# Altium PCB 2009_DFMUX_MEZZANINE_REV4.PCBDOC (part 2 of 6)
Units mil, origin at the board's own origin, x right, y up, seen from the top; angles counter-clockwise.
Board outline 4922.86 x 3627.76 mil, 6 copper layers (Top Layer, Internal Plane 1, Mid-Layer 1, Internal Plane 2, Mid-Layer 2, Bottom Layer); 519 components, 606 nets, 2175 pads, 757 vias.
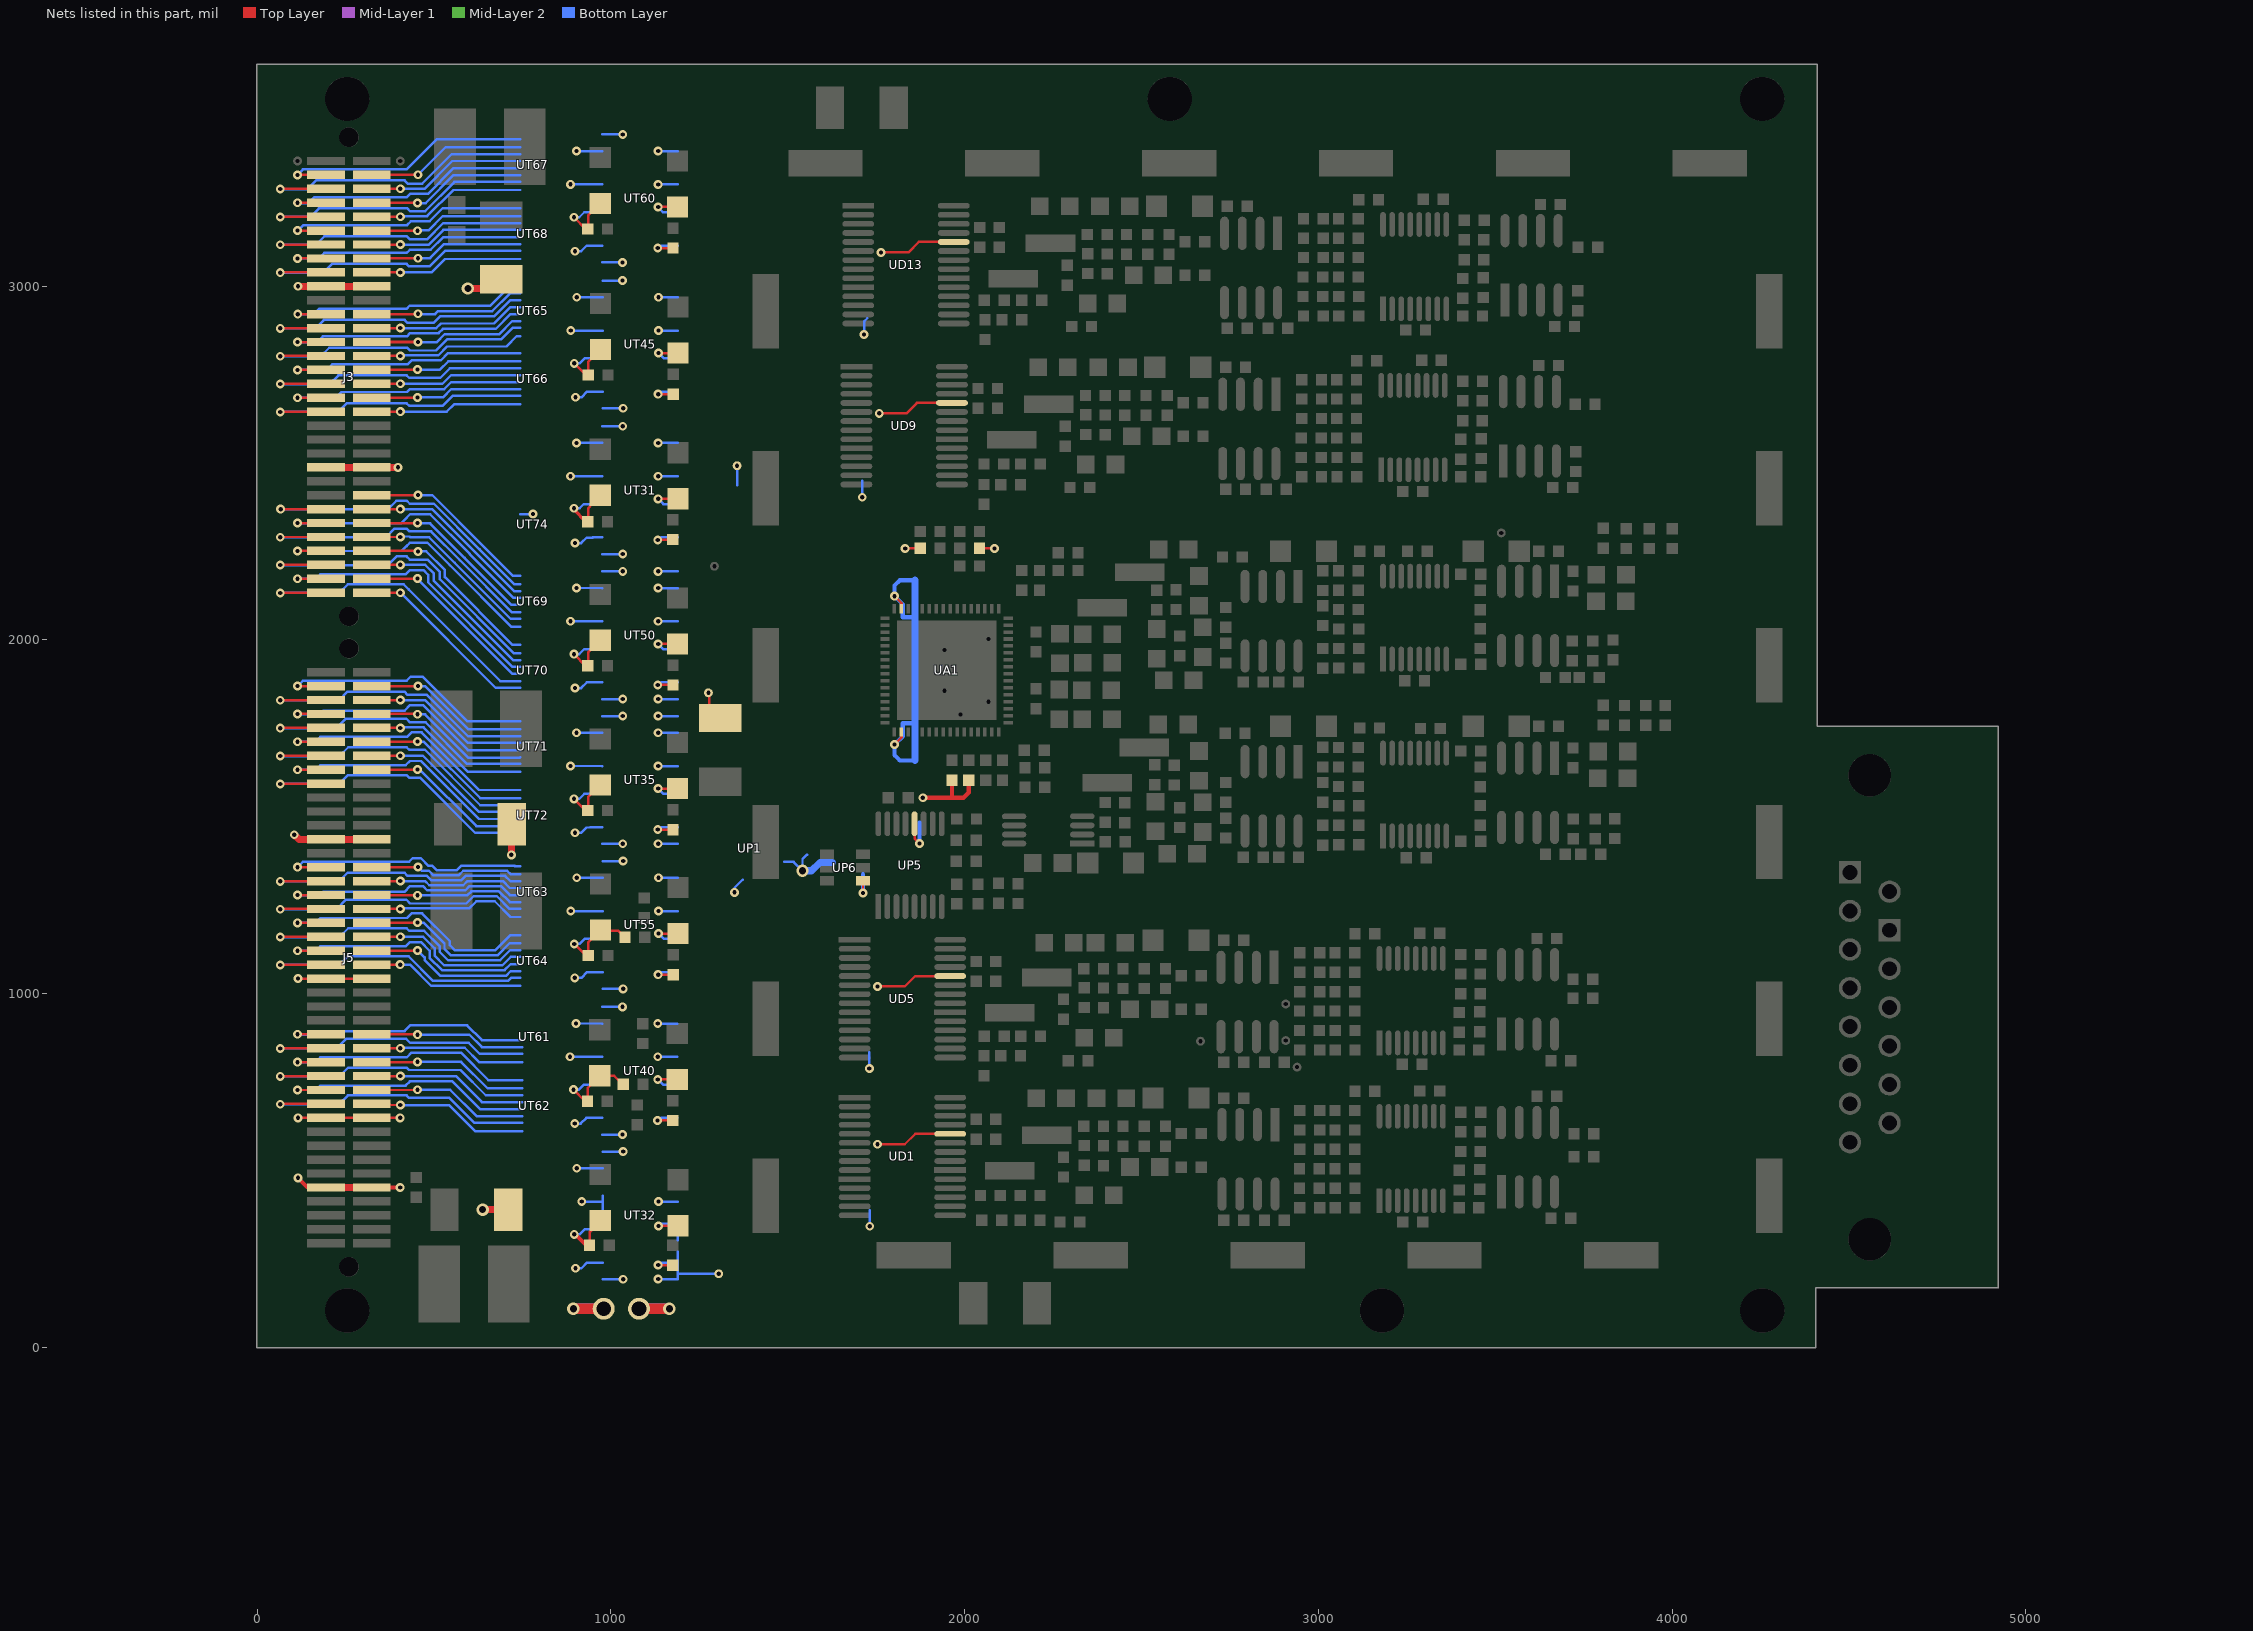
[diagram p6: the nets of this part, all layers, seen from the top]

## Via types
v1: diameter 25, hole 12, Top Layer to Bottom Layer, 692 vias
v2: diameter 40, hole 20, Top Layer to Bottom Layer, 39 vias
v3: diameter 35, hole 20, Top Layer to Bottom Layer, 23 vias
v4: diameter 22, hole 12, Top Layer to Bottom Layer, 3 vias

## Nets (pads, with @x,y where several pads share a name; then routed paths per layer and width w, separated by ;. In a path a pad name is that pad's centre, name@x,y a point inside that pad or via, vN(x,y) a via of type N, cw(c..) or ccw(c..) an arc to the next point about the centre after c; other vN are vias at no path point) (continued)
COMB1_DATA4: J5.53 UT61.12 | length 743.5
  Top Layer w7: v1(114.33,884.83) J5.53@194.63,884.83
  Bottom Layer w7: v1(114.33,884.83) 115.3,883.87 176.63,883.87 186.63,893.87 416.63,893.87 432.63,909.87 593.77,909.87 635.27,868.37 UT61.12@749.13,868.37
COMB1_DATA5: J5.54 UT61.11 | length 439.7
  Top Layer w7: J5.54@324.55,884.83 452.67,884.83 v1(453.63,883.87)
  Bottom Layer w7: v1(453.63,883.87) 599.77,883.87 635.27,848.37 UT61.11@749.13,848.37
COMB1_DATA6: J5.55 UT61.10 | length 841.8
  Top Layer w7: v1(65.55,844.7) 66.32,845.47 J5.55@194.63,845.47
  Bottom Layer w7: v1(65.55,844.7) 224.47,844.7 251.63,871.87 421.63,871.87 432.63,860.87 597.77,860.87 629.27,829.37 UT61.10@749.13,829.37
COMB1_DATA7: J5.56 UT61.9 | length 441.9
  Top Layer w7: J5.56@324.55,845.47 v1(404.85,845.47)
  Bottom Layer w7: v1(404.85,845.47) 406.45,846.87 586.77,846.87 627.27,806.37 UT61.9@749.13,806.37
COMB1_DATA8: J5.57 UT62.16 | length 758.5
  Top Layer w7: v1(114.33,806.1) J5.57@194.63,806.1
  Bottom Layer w7: v1(114.33,806.1) 114.57,805.87 164.63,805.87 178.63,819.87 423.63,819.87 436.63,832.87 575.77,832.87 653.27,755.37 UT62.16@749.13,755.37
COMB1_DATA9: J5.58 UT62.15 | length 455.8
  Top Layer w7: J5.58@324.55,806.1 452.87,806.1 v1(453.63,806.87)
  Bottom Layer w7: v1(453.63,806.87) 576.77,806.87 651.27,732.37 UT62.15@749.13,732.37
COMB1_DATA10: J5.59 UT62.14 | length 855.8
  Top Layer w7: v1(65.55,765.97) 66.32,766.73 J5.59@194.63,766.73
  Bottom Layer w7: v1(65.55,765.97) 232.73,765.97 257.63,790.87 422.63,790.87 429.63,783.87 574.77,783.87 646.27,712.37 UT62.14@749.13,712.37
COMB1_DATA11: J5.60 UT62.13 | length 455
  Top Layer w7: J5.60@324.55,766.73 v1(404.85,766.73)
  Bottom Layer w7: v1(404.85,766.73) 561.9,766.73 635.27,693.37 UT62.13@749.13,693.37
COMB1_DATA12: J5.61 UT62.12 | length 757.8
  Top Layer w7: v1(114.33,727.37) J5.61@194.63,727.37
  Bottom Layer w7: v1(114.33,727.37) 166.13,727.37 178.63,739.87 419.63,739.87 431.63,751.87 551.77,751.87 630.27,673.37 UT62.12@749.13,673.37
COMB1_DATA13: J5.62 UT62.11 | length 455.9
  Top Layer w7: J5.62@324.55,727.37 452.87,727.37 v1(453.63,728.13)
  Bottom Layer w7: v1(453.63,728.13) 545.5,728.13 620.27,653.37 UT62.11@749.13,653.37
COMB1_DATA14: J5.63 UT62.10 | length 855.3
  Top Layer w7: v1(65.55,687.23) 66.32,688 J5.63@194.63,688
  Bottom Layer w7: v1(65.55,687.23) 232,687.23 256.63,711.87 422.63,711.87 429.63,704.87 543.77,704.87 614.27,634.37 UT62.10@749.13,634.37
COMB1_DATA15: J5.64 UT62.9 | length 455
  Top Layer w7: J5.64@324.55,688 v1(404.85,684.73)
  Bottom Layer w7: v1(404.85,684.73) 542.9,684.73 616.27,611.37 UT62.9@749.13,611.37
COMB2_DATA0: J5.29 UT63.16 | length 740.4
  Top Layer w7: v1(114.33,1357.23) J5.29@194.63,1357.23
  Bottom Layer w7: v1(114.33,1357.23) 129.63,1372.53 429.8,1372.53 439.63,1382.37 463.27,1382.37 484.63,1361 495.63,1361 508.63,1348 563.63,1348 576.63,1361 727.63,1361 728.27,1360.37 UT63.16@744.13,1360.37
COMB2_DATA1: J5.30 UT63.15 | length 438.8
  Top Layer w7: J5.30@324.55,1357.23 453.33,1357.23 453.63,1357.53 v1(454.63,1357.53)
  Bottom Layer w7: v1(454.63,1357.53) 455.1,1357.53 465.63,1347 485.63,1347 498.63,1334 569.63,1334 582.63,1347 706.63,1347 716.27,1337.37 UT63.15@744.13,1337.37
COMB2_DATA2: J5.31 UT63.14 | length 838.5
  Top Layer w7: v1(65.55,1317.1) 66.32,1317.87 J5.31@194.63,1317.87
  Bottom Layer w7: v1(65.55,1317.1) 231.2,1317.1 255.63,1341.53 416.63,1341.53 425.63,1332.53 480.1,1332.53 492.63,1320 576.63,1320 589.17,1332.53 701.1,1332.53 716.27,1317.37 UT63.14@744.13,1317.37
COMB2_DATA3: J5.32 UT63.13 | length 437.5
  Top Layer w7: J5.32@324.55,1317.87 v1(404.85,1317.87)
  Bottom Layer w7: v1(404.85,1317.87) 474.77,1317.87 486.63,1306 582.63,1306 594.5,1317.87 694.63,1317.87 714.13,1298.37 UT63.13@744.13,1298.37
COMB2_DATA4: J5.33 UT63.12 | length 741.2
  Top Layer w7: v1(114.33,1278.5) J5.33@194.63,1278.5
  Bottom Layer w7: v1(114.33,1278.5) 115.3,1277.53 176.63,1277.53 186.63,1287.53 416.63,1287.53 432.63,1303.53 469.1,1303.53 480.63,1292 588.63,1292 600.17,1303.53 689.1,1303.53 714.27,1278.37 UT63.12@744.13,1278.37
COMB2_DATA5: J5.34 UT63.11 | length 437.4
  Top Layer w7: J5.34@324.55,1278.5 452.67,1278.5 v1(453.63,1277.53)
  Bottom Layer w7: v1(453.63,1277.53) 454.1,1278 594.63,1278 605.63,1289 683.63,1289 714.27,1258.37 UT63.11@744.13,1258.37
COMB2_DATA6: J5.35 UT63.10 | length 847
  Top Layer w7: v1(65.55,1238.37) 66.32,1239.13 J5.35@194.63,1239.13
  Bottom Layer w7: v1(65.55,1238.37) 224.47,1238.37 251.63,1265.53 421.63,1265.53 432.63,1254.53 591.17,1254.53 611.63,1275 677.63,1275 713.27,1239.37 UT63.10@744.13,1239.37
COMB2_DATA7: J5.36 UT63.9 | length 447.1
  Top Layer w7: J5.36@324.55,1239.13 v1(404.85,1239.13)
  Bottom Layer w7: v1(404.85,1239.13) 406.45,1240.53 599.17,1240.53 619.63,1261 671.63,1261 716.27,1216.37 UT63.9@744.13,1216.37
COMB2_DATA8: J5.37 UT64.16 | length 789.1
  Top Layer w7: v1(114.33,1199.77) J5.37@194.63,1199.77
  Bottom Layer w7: v1(114.33,1199.77) 114.57,1199.53 164.63,1199.53 178.63,1213.53 423.63,1213.53 436.63,1226.53 466.1,1226.53 544.63,1148 544.63,1137 559.63,1122 672.63,1122 716,1165.37 UT64.16@744.13,1165.37
COMB2_DATA9: J5.38 UT64.15 | length 481.3
  Top Layer w7: J5.38@324.55,1199.77 452.87,1199.77 v1(453.63,1200.53)
  Bottom Layer w7: v1(453.63,1200.53) 470.1,1200.53 529.63,1141 529.63,1126 547.63,1108 679.63,1108 714,1142.37 UT64.15@744.13,1142.37
COMB2_DATA10: J5.39 UT64.14 | length 876.9
  Top Layer w7: v1(65.55,1159.63) 66.32,1160.4 J5.39@194.63,1160.4
  Bottom Layer w7: v1(65.55,1159.63) 232.73,1159.63 257.63,1184.53 422.63,1184.53 429.63,1177.53 472.1,1177.53 515.63,1134 515.63,1118 539.63,1094 686.63,1094 715,1122.37 UT64.14@744.13,1122.37
COMB2_DATA11: J5.40 UT64.13 | length 474.9
  Top Layer w7: J5.40@324.55,1160.4 v1(404.85,1160.4)
  Bottom Layer w7: v1(404.85,1160.4) 469.23,1160.4 501.63,1128 501.63,1107 528.63,1080 693.63,1080 717,1103.37 UT64.13@744.13,1103.37
COMB2_DATA12: J5.41 UT64.12 | length 772.1
  Top Layer w7: v1(114.33,1121.03) J5.41@194.63,1121.03
  Bottom Layer w7: v1(114.33,1121.03) 166.13,1121.03 178.63,1133.53 419.63,1133.53 431.63,1145.53 463.1,1145.53 487.63,1121 487.63,1101 522.63,1066 699.63,1066 717,1083.37 UT64.12@744.13,1083.37
COMB2_DATA13: J5.42 UT64.11 | length 459.3
  Top Layer w7: J5.42@324.55,1121.03 452.87,1121.03 v1(453.63,1121.8)
  Bottom Layer w7: v1(453.63,1121.8) 453.83,1121.8 473.63,1102 473.63,1095 518.63,1050 703.63,1050 717,1063.37 UT64.11@744.13,1063.37
COMB2_DATA14: J5.43 UT64.10 | length 850.5
  Top Layer w7: v1(65.55,1080.9) 66.32,1081.67 J5.43@194.63,1081.67
  Bottom Layer w7: v1(65.55,1080.9) 232,1080.9 256.63,1105.53 428.1,1105.53 497.63,1036 709.63,1036 718,1044.37 UT64.10@744.13,1044.37
COMB2_DATA15: J5.44 UT64.9 | length 444.6
  Top Layer w7: J5.44@324.55,1081.67 v1(404.33,1081.67)
  Bottom Layer w7: v1(404.33,1081.67) 431.97,1081.67 492.27,1021.37 UT64.9@744.13,1021.37
COMB3_DATA0: J3.23 UT65.16 | length 746.9
  Top Layer w7: v1(114.67,2920.4) J3.23@194.63,2920.4
  Bottom Layer w7: v1@112.03,2918 v1(114.67,2920.4) ; v1@114.7,2920.37 159.63,2920.37 175.63,2936.37 423.3,2936.37 431.3,2944.37 659.63,2944.37 718,3002.37 UT65.16@744.13,3002.37
COMB3_DATA1: J3.24 UT65.15 | length 446.8
  Top Layer w7: J3.24@324.55,2920.4 453.33,2920.4 v1@453.63,2920.7 ; v1@453.63,2920.7 454.63,2920.7 v1(454.63,2921.37) 453.63,2921.37 v1@453.63,2920.7
  Bottom Layer w7: v1(454.63,2921.37) 455.63,2920.37 502.63,2920.37 503.3,2920.7 511.6,2929 664.63,2929 715,2979.37 UT65.15@744.13,2979.37
COMB3_DATA2: J3.25 UT65.14 | length 847.9
  Top Layer w7: v1(65.55,2880.27) 66.32,2881.03 J3.25@194.63,2881.03
  Bottom Layer w7: v1(65.55,2880.27) 164.53,2880.27 188.63,2904.37 416.97,2904.37 425.63,2895.7 498.97,2895.7 517.27,2914 669.63,2914 715,2959.37 UT65.14@744.13,2959.37
COMB3_DATA3: J3.26 UT65.13 | length 444.2
  Top Layer w7: J3.26@324.55,2881.03 v1(404.85,2881.03)
  Bottom Layer w7: v1(404.85,2881.03) 506.3,2881.03 519.27,2894 669.63,2894 716,2940.37 UT65.13@744.13,2940.37
COMB3_DATA4: J3.27 UT65.12 | length 743.5
  Top Layer w7: v1(114.33,2841.67) J3.27@194.63,2841.67
  Bottom Layer w7: v1(114.33,2841.67) 115.3,2840.7 168.73,2840.7 185.73,2857.37 423.63,2857.37 432.63,2866.7 512.97,2866.7 525.27,2879 674.63,2879 716,2920.37 UT65.12@744.13,2920.37
COMB3_DATA5: J3.28 UT65.11 | length 576.5
  Top Layer w7: J3.28@324.55,2841.67 324.88,2842 v1(454.63,2842) 453.97,2841.67 J3.28@324.55,2841.67
  Bottom Layer w7: v1@454,2841.37 v1(454.63,2842) 453.97,2841.67 507.93,2841.67 530.27,2864 684.63,2864 721,2900.37 UT65.11@744.13,2900.37
COMB3_DATA6: J3.29 UT65.10 | length 847.2
  Top Layer w7: v1(65.55,2801.53) 66.32,2802.3 J3.29@194.63,2802.3
  Bottom Layer w7: v1(65.55,2801.53) 179.65,2801.53 203.82,2825.37 424.63,2825.37 432.63,2817.7 505.97,2817.7 537.27,2849 689.63,2849 722,2881.37 UT65.10@744.13,2881.37
COMB3_DATA7: J3.30 UT65.9 | length 442.8
  Top Layer w7: J3.30@324.55,2802.3 v1(404.85,2802.3)
  Bottom Layer w7: v1(404.85,2802.3) 406.45,2803.7 511.97,2803.7 537.27,2829 704.63,2829 734,2858.37 UT65.9@744.13,2858.37
COMB3_DATA8: J3.31 UT66.16 | length 729.8
  Top Layer w7: v1(114.33,2762.93) J3.31@194.63,2762.93
  Bottom Layer w7: v1(114.33,2762.93) 114.57,2762.7 195.97,2762.7 210.97,2777.37 211.97,2778.37 425.3,2778.37 436.63,2789.7 518.97,2789.7 539.63,2810.37 UT66.16@744.13,2810.37
COMB3_DATA9: J3.32 UT66.15 | length 429.7
  Top Layer w7: J3.32@324.55,2762.93 452.87,2762.93 v1(453.63,2763.7)
  Bottom Layer w7: v1(453.63,2763.7) 516.97,2763.7 540.63,2787.37 UT66.15@744.13,2787.37
COMB3_DATA10: J3.33 UT66.14 | length 831.8
  Top Layer w7: v1(65.55,2722.8) 66.32,2723.57 J3.33@194.63,2723.57
  Bottom Layer w7: v1(65.55,2722.8) 204.9,2722.8 229.8,2747.37 422.63,2747.37 429.63,2740.7 517.97,2740.7 544.63,2767.37 UT66.14@744.13,2767.37
COMB3_DATA11: J3.34 UT66.13 | length 429.9
  Top Layer w7: J3.34@324.55,2723.57 v1(404.85,2723.57)
  Bottom Layer w7: v1(404.85,2723.57) 523.83,2723.57 548.63,2748.37 UT66.13@744.13,2748.37
COMB3_DATA12: J3.35 UT66.12 | length 728.4
  Top Layer w7: v1(114.33,2684.2) J3.35@194.63,2684.2
  Bottom Layer w7: v1(114.33,2684.2) 222.3,2684.2 238.8,2700.37 423.63,2700.37 431.63,2708.7 528.97,2708.7 548.63,2728.37 UT66.12@744.13,2728.37
COMB3_DATA13: J3.36 UT66.11 | length 429.6
  Top Layer w7: J3.36@324.55,2684.2 452.87,2684.2 v1(453.63,2684.97)
  Bottom Layer w7: v1(453.63,2684.97) 525.23,2684.97 548.63,2708.37 UT66.11@744.13,2708.37
COMB3_DATA14: J3.37 UT66.10 | length 832.1
  Top Layer w7: v1(65.55,2644.07) 66.32,2644.83 J3.37@194.63,2644.83
  Bottom Layer w7: v1(65.55,2644.07) 228.15,2644.07 252.78,2668.37 422.63,2668.37 429.63,2661.7 524.97,2661.7 552.63,2689.37 UT66.10@744.13,2689.37
COMB3_DATA15: J3.38 UT66.9 | length 428.5
  Top Layer w7: J3.38@324.55,2644.83 v1(404.85,2644.83)
  Bottom Layer w7: v1(404.85,2644.83) 536.1,2644.83 557.63,2666.37 UT66.9@744.13,2666.37
COMB4_DATA0: J3.3 UT67.16 | length 752.1
  Top Layer w7: v1(114.33,3314.07) J3.3@194.63,3314.07
  Bottom Layer w7: v1(114.33,3314.07) 129.63,3329.37 422.63,3329.37 508.63,3415.37 UT67.16@744.13,3415.37
COMB4_DATA1: J3.4 UT67.15 | length 452
  Top Layer w7: J3.4@324.55,3314.07 453.33,3314.07 453.63,3314.37 v1(454.63,3314.37)
  Bottom Layer w7: v1(454.63,3314.37) 532.63,3392.37 UT67.15@744.13,3392.37
COMB4_DATA2: J3.5 UT67.14 | length 856.2
  Top Layer w7: v1(65.55,3273.93) 66.32,3274.7 J3.5@194.63,3274.7
  Bottom Layer w7: v1(65.55,3273.93) 142.2,3273.93 166.63,3298.37 416.63,3298.37 425.63,3289.37 466.63,3289.37 549.63,3372.37 UT67.14@744.13,3372.37
COMB4_DATA3: J3.6 UT67.13 | length 452.2
  Top Layer w7: J3.6@324.55,3274.7 v1(404.85,3274.7)
  Bottom Layer w7: v1(404.85,3274.7) 472.97,3274.7 551.63,3353.37 UT67.13@744.13,3353.37
COMB4_DATA4: J3.7 UT67.12 | length 751.5
  Top Layer w7: v1(114.33,3235.33) J3.7@194.63,3235.33
  Bottom Layer w7: v1(114.33,3235.33) 115.3,3234.37 145.63,3234.37 162.63,3251.37 423.63,3251.37 432.63,3260.37 482.63,3260.37 555.63,3333.37 UT67.12@744.13,3333.37
COMB4_DATA5: J3.8 UT67.11 | length 452.7
  Top Layer w7: J3.8@324.55,3235.33 452.67,3235.33 v1(453.63,3234.37)
  Bottom Layer w7: v1(453.63,3234.37) 476.63,3234.37 555.63,3313.37 UT67.11@744.13,3313.37
COMB4_DATA6: J3.9 UT67.10 | length 855.7
  Top Layer w7: v1(65.55,3195.2) 66.32,3195.97 J3.9@194.63,3195.97
  Bottom Layer w7: v1(65.55,3195.2) 150.47,3195.2 174.63,3219.37 424.63,3219.37 432.63,3211.37 474.63,3211.37 557.63,3294.37 UT67.10@744.13,3294.37
COMB4_DATA7: J3.10 UT67.9 | length 451
  Top Layer w7: J3.10@324.55,3195.97 v1(404.85,3195.97)
  Bottom Layer w7: v1(404.85,3195.97) 405.25,3196.37 405.85,3196.37 406.45,3197.37 480.63,3197.37 554.63,3271.37 UT67.9@744.13,3271.37
COMB4_DATA8: J3.11 UT68.16 | length 736.8
  Top Layer w7: v1(114.33,3156.6) J3.11@194.63,3156.6
  Bottom Layer w7: v1(114.33,3156.6) 114.57,3156.37 130.57,3172.37 423.83,3172.37 434.63,3183 487.63,3183 524.63,3220.37 UT68.16@744.13,3220.37
COMB4_DATA9: J3.12 UT68.15 | length 437.9
  Top Layer w7: J3.12@324.55,3156.6 454.03,3156.6 v1(453.63,3156)
  Bottom Layer w7: v1(453.63,3156) 454.03,3156.6 454.8,3157.37 484.63,3157.37 524.63,3197.37 UT68.15@744.13,3197.37
COMB4_DATA10: J3.13 UT68.14 | length 840.1
  Top Layer w7: v1(65.55,3116.47) 66.32,3117.23 J3.13@194.63,3117.23
  Bottom Layer w7: v1(65.55,3116.47) 165.73,3116.47 189.63,3140.37 423.63,3140.37 432,3132 480.27,3132 525.63,3177.37 UT68.14@744.13,3177.37
COMB4_DATA11: J3.14 UT68.13 | length 436.6
  Top Layer w7: J3.14@324.55,3117.23 v1(404.85,3117.23)
  Bottom Layer w7: v1(404.85,3117.23) 485.5,3117.23 526.63,3158.37 UT68.13@744.13,3158.37
COMB4_DATA12: J3.15 UT68.12 | length 735.2
  Top Layer w7: v1(114.33,3077.87) J3.15@194.63,3077.87
  Bottom Layer w7: v1(114.33,3077.87) 174.13,3077.87 189.63,3093.37 422.63,3093.37 431.63,3102.37 490.63,3102.37 526.63,3138.37 UT68.12@744.13,3138.37
COMB4_DATA13: J3.16 UT68.11 | length 568.7
  Top Layer w7: J3.16@324.55,3077.87 453.33,3077.87 453.83,3078.37 v1(454.63,3078.37) 453.63,3078.63 452.87,3077.87 J3.16@324.55,3077.87
  Bottom Layer w7: v1(454.63,3078.37) 453.63,3078.63 488.9,3078.63 528.63,3118.37 UT68.11@744.13,3118.37
COMB4_DATA14: J3.17 UT68.10 | length 839.3
  Top Layer w7: v1(65.55,3037.73) 66.32,3038.5 J3.17@194.63,3038.5
  Bottom Layer w7: v1(65.55,3037.73) 187,3037.73 211.63,3062.37 422.63,3062.37 429.63,3055.37 487.63,3055.37 531.63,3099.37 UT68.10@744.13,3099.37
COMB4_DATA15: J3.18 UT68.9 | length 435.3
  Top Layer w7: J3.18@324.55,3038.5 v1(404.85,3038.5)
  Bottom Layer w7: v1(404.85,3038.5) 492.77,3038.5 530.63,3076.37 UT68.9@744.13,3076.37
DEMODA_DATA0: J5.3 UT71.16 | length 773.3
  Top Layer w7: v1(114.33,1869) J5.3@194.63,1869
  Bottom Layer w7: v1(114.33,1869) 129.63,1884.3 422.63,1884.3 434.3,1895.97 468.03,1895.97 593.63,1770.37 UT71.16@744.13,1770.37
DEMODA_DATA1: J5.4 UT71.15 | length 470.2
  Top Layer w7: J5.4@324.55,1869 453.33,1869 453.63,1869.3 v1(454.63,1869.3)
  Bottom Layer w7: v1(454.63,1869.3) 474.7,1869.3 596.63,1747.37 UT71.15@744.13,1747.37
DEMODA_DATA2: J5.5 UT71.14 | length 870.3
  Top Layer w7: v1(65.55,1828.87) 66.32,1829.63 J5.5@194.63,1829.63
  Bottom Layer w7: v1(65.55,1828.87) 231.2,1828.87 255.63,1853.3 416.63,1853.3 425.63,1844.3 479.7,1844.3 596.63,1727.37 UT71.14@744.13,1727.37
DEMODA_DATA3: J5.6 UT71.13 | length 469.8
  Top Layer w7: J5.6@324.55,1829.63 v1(404.85,1829.63)
  Bottom Layer w7: v1(404.85,1829.63) 474.37,1829.63 595.63,1708.37 UT71.13@744.13,1708.37
DEMODA_DATA4: J5.7 UT71.12 | length 773.8
  Top Layer w7: v1(114.33,1790.27) J5.7@194.63,1790.27
  Bottom Layer w7: v1(114.33,1790.27) 115.3,1789.3 176.63,1789.3 186.63,1799.3 416.63,1799.3 432.63,1815.3 468.7,1815.3 595.63,1688.37 UT71.12@744.13,1688.37
DEMODA_DATA5: J5.8 UT71.11 | length 471.7
  Top Layer w7: J5.8@324.55,1790.27 452.67,1790.27 v1(453.63,1789.3)
  Bottom Layer w7: v1(453.63,1789.3) 474.7,1789.3 597.63,1666.37 742.13,1666.37 UT71.11@744.13,1668.37
DEMODA_DATA6: J5.9 UT71.10 | length 872.2
  Top Layer w7: v1(65.55,1750.13) 66.32,1750.9 J5.9@194.63,1750.9
  Bottom Layer w7: v1(65.55,1750.13) 224.47,1750.13 251.63,1777.3 421.63,1777.3 432.63,1766.3 476.7,1766.3 593.63,1649.37 UT71.10@744.13,1649.37
DEMODA_DATA7: J5.10 UT71.9 | length 472.3
  Top Layer w7: J5.10@324.55,1750.9 v1(404.85,1750.9)
  Bottom Layer w7: v1(404.85,1750.9) 406.45,1752.3 470.7,1752.3 596.63,1626.37 UT71.9@744.13,1626.37
DEMODA_DATA8: J5.11 UT72.16 | length 788.9
  Top Layer w7: v1(114.33,1711.53) J5.11@194.63,1711.53
  Bottom Layer w7: v1(114.33,1711.53) 114.57,1711.3 164.63,1711.3 178.63,1725.3 423.63,1725.3 436.63,1738.3 464.7,1738.3 627.63,1575.37 UT72.16@744.13,1575.37
DEMODA_DATA9: J5.12 UT72.15 | length 486.1
  Top Layer w7: J5.12@324.55,1711.53 452.87,1711.53 v1(453.63,1712.3)
  Bottom Layer w7: v1(453.63,1712.3) 470.7,1712.3 630.63,1552.37 UT72.15@744.13,1552.37
DEMODA_DATA10: J5.13 UT72.14 | length 886.2
  Top Layer w7: v1(65.55,1671.4) 66.32,1672.17 J5.13@194.63,1672.17
  Bottom Layer w7: v1(65.55,1671.4) 232.73,1671.4 257.63,1696.3 422.63,1696.3 429.63,1689.3 473.7,1689.3 630.63,1532.37 UT72.14@744.13,1532.37
DEMODA_DATA11: J5.14 UT72.13 | length 485.4
  Top Layer w7: J5.14@324.55,1672.17 v1(404.85,1672.17)
  Bottom Layer w7: v1(404.85,1672.17) 468.83,1672.17 627.63,1513.37 UT72.13@744.13,1513.37
DEMODA_DATA12: J5.15 UT72.12 | length 788.2
  Top Layer w7: v1(114.33,1632.8) J5.15@194.63,1632.8
  Bottom Layer w7: v1(114.33,1632.8) 166.13,1632.8 178.63,1645.3 419.63,1645.3 431.63,1657.3 463.7,1657.3 627.63,1493.37 UT72.12@744.13,1493.37
DEMODA_DATA13: J5.16 UT72.11 | length 486.3
  Top Layer w7: J5.16@324.55,1632.8 452.87,1632.8 v1(453.63,1633.57)
  Bottom Layer w7: v1(453.63,1633.57) 459.43,1633.57 619.63,1473.37 UT72.11@744.13,1473.37
DEMODA_DATA14: J5.17 UT72.10 | length 885.7
  Top Layer w7: v1(65.55,1592.67) 66.32,1593.43 J5.17@194.63,1593.43
  Bottom Layer w7: v1(65.55,1592.67) 232,1592.67 256.63,1617.3 422.63,1617.3 429.63,1610.3 460.7,1610.3 616.63,1454.37 UT72.10@744.13,1454.37
DEMODB_DATA0: J3.50 UT69.16 | length 514.6
  Top Layer w7: J3.50@324.55,2408.63 453.33,2408.63 453.63,2408.93 v1(454.63,2408.93)
  Bottom Layer w7: v1(454.63,2408.93) 495.07,2408.93 642.63,2261.37 642.63,2261 723.27,2180.37 UT69.16@744.13,2180.37
DEMODB_DATA1: J3.51 UT69.15 | length 915.1
  Top Layer w7: v1@64.9,2369.27 v1(66.55,2369.27) J3.51@194.63,2369.27
  Bottom Layer w7: v1(66.55,2369.27) 369.98,2369.27 393.62,2393.13 422.63,2393.13 431.4,2384.37 499.63,2384.37 628.63,2255.37 628.63,2255 726.27,2157.37 UT69.15@744.13,2157.37
DEMODB_DATA2: J3.52 UT69.14 | length 515.9
  Top Layer w7: J3.52@324.55,2369.27 v1(404.85,2369.27)
  Bottom Layer w7: v1(404.85,2369.27) 494.73,2369.27 614.63,2249.37 614.63,2249 726.27,2137.37 UT69.14@744.13,2137.37
DEMODB_DATA3: J3.53 UT69.13 | length 819.5
  Top Layer w7: v1(114.33,2329.9) J3.53@194.63,2329.9
  Bottom Layer w7: v1(114.33,2329.9) 115.3,2328.93 406.57,2328.93 416.57,2338.93 416.63,2338.93 432.63,2354.93 489.07,2354.93 600.63,2243.37 600.63,2243 725.27,2118.37 UT69.13@744.13,2118.37
DEMODB_DATA4: J3.54 UT69.12 | length 516.1
  Top Layer w7: J3.54@324.55,2329.9 453.17,2329.9 v1(453.63,2330.37)
  Bottom Layer w7: v1(453.63,2330.37) 455.07,2328.93 489.07,2328.93 586.63,2231.37 586.63,2231 719.27,2098.37 UT69.12@744.13,2098.37
DEMODB_DATA5: J3.55 UT69.11 | length 916.2
  Top Layer w7: v1(65.55,2289.77) 66.32,2290.53 J3.55@194.63,2290.53
  Bottom Layer w7: v1(65.55,2289.77) 363.63,2289.77 388.27,2314.4 422.63,2314.4 430.67,2306.37 491.63,2306.37 572.63,2225.37 572.63,2225 719.27,2078.37 UT69.11@744.13,2078.37
DEMODB_DATA6: J3.56 UT69.10 | length 516.9
  Top Layer w7: J3.56@324.55,2290.53 v1(404.85,2290.53)
  Bottom Layer w7: v1(404.85,2290.53) 405.25,2290.93 405.85,2290.93 406.45,2291.93 431.07,2291.93 433.63,2289.37 486.63,2289.37 558.63,2217.37 558.63,2217 716.27,2059.37 UT69.10@744.13,2059.37
DEMODB_DATA7: J3.57 UT69.9 | length 818.8
  Top Layer w7: v1(114.33,2251.17) J3.57@194.63,2251.17
  Bottom Layer w7: v1(114.33,2251.17) 114.57,2250.93 408.57,2250.93 422.57,2264.93 422.8,2264.93 431.8,2274.37 481.63,2274.37 544.63,2211.37 544.63,2211 719.27,2036.37 UT69.9@744.13,2036.37
DEMODB_DATA8: J3.58 UT70.16 | length 542.6
  Top Layer w7: J3.58@324.55,2251.17 452.87,2251.17 v1@454.63,2249.4
  Bottom Layer w7: v1(454.63,2249.37) 455.2,2250.37 477.63,2250.37 530.63,2197.37 530.63,2177 722.27,1985.37 UT70.16@744.13,1985.37
DEMODB_DATA9: J3.59 UT70.15 | length 943.4
  Top Layer w7: v1(65.55,2211.03) 66.32,2211.8 J3.59@194.63,2211.8
  Bottom Layer w7: v1(65.55,2211.03) 369.67,2211.03 394.3,2235.67 422.63,2235.67 431.63,2226.37 481.63,2226.37 516.63,2191.37 516.63,2171 725.27,1962.37 UT70.15@744.13,1962.37
DEMODB_DATA10: J3.60 UT70.14 | length 545.9
  Top Layer w7: J3.60@324.55,2211.8 v1(404.85,2211.8)
  Mid-Layer 1 w7: v1@403.28,2213.37 v1(404.85,2211.8)
  Bottom Layer w7: v1(404.85,2211.8) 475.2,2211.8 498.63,2188.37 498.63,2167 723.27,1942.37 UT70.14@744.13,1942.37
DEMODB_DATA11: J3.61 UT70.13 | length 846.1
  Top Layer w7: v1(114.33,2172.43) J3.61@194.63,2172.43
  Bottom Layer w7: v1(114.33,2172.43) 166.13,2172.43 178.63,2184.93 419.63,2184.93 431.63,2196.93 470.07,2196.93 483.63,2183.37 483.63,2162 722.27,1923.37 UT70.13@744.13,1923.37
DEMODB_DATA12: J3.62 UT70.12 | length 532.5
  Top Layer w7: J3.62@324.55,2172.43 452.87,2172.43 v1(453.63,2173.2)
  Bottom Layer w7: v1(453.63,2173.2) 453.8,2173.2 453.8,2171.83 722.27,1903.37 UT70.12@744.13,1903.37
DEMODB_DATA13: J3.63 UT70.11 | length 931.7
  Top Layer w7: v1(65.55,2132.3) 66.32,2133.07 J3.63@194.63,2133.07
  Bottom Layer w7: v1(65.55,2132.3) 232,2132.3 256.63,2156.93 414.07,2156.93 428.63,2142.37 428.63,2142 687.27,1883.37 UT70.11@744.13,1883.37
DEMODB_DATA14: J3.64 UT70.10 | length 531.1
  Top Layer w7: J3.64@324.55,2133.07 v1(404.85,2133.07)
  Bottom Layer w7: v1(404.85,2133.07) 405.93,2133.07 407.63,2131.37 407.63,2131 674.27,1864.37 UT70.10@744.13,1864.37
GND_DIG: CA7.1 CA25.2 CA33.1 CA44.2 CA45.2 CP3.1 CP6.2 CP7.2 CP21.2 CP22.1 CT27.2 CT28.1 CT31.2 CT32.1 CT33.2 CT34.1 CT37.2 CT38.1 CT41.2 CT42.1 CT45.2 CT46.1 CT49.2 CT50.1 CT53.2 CT54.1 J1.2 pad.1@1275.63,1850 pad.1@1304.63,208 pad.1@1356.63,2492 RA3.1 RA5.1 RA54.2 RP6.2 RP8.2 RP35.2 RP36.1 RP37.1 RP38.1 RP39.1 RP40.1 UA1.31 UA1.50 UD1.24 UD5.24 UD9.24 UD13.24 UP1.4 UP5.12 UP6.1 UT31.4 UT31.10 UT31.15 UT31.21 UT31.25 UT31.48 UT32.10 UT32.14 UT32.15 UT32.16 UT32.17 UT32.19 UT32.20 UT32.21 UT32.22 UT32.23 UT32.24 UT32.25 UT32.48 UT35.1 UT35.4 UT35.10 UT35.15 UT35.21 UT35.24 UT35.25 UT35.48 UT40.4 UT40.10 UT40.15 UT40.21 UT40.25 UT40.48 UT45.4 UT45.10 UT45.15 UT45.21 UT45.25 UT45.48 UT50.1 UT50.4 UT50.10 UT50.15 UT50.21 UT50.24 UT50.25 UT50.48 UT55.4 UT55.10 UT55.15 UT55.21 UT55.25 UT55.48 UT60.4 UT60.10 UT60.15 UT60.21 UT60.25 UT60.48 | length 9243
  Top Layer w7: v1(1131.63,641.37) CT38.1@1174.63,641.37 ; v1(1132.63,1463.37) CT34.1@1175.63,1463.37 ; v1(1132.63,3107.37) CT54.1@1175.63,3107.37 ; v1(1133.63,1053.37) CT50.1@1176.63,1053.37 ; v1(1134.63,343) 1134.27,343.37 CT31.2@1189.63,343.37 ; pad.1@1275.63,1850 1277.63,1852 1277.63,1815 1309.63,1783 CP6.2@1309.63,1779 ; v1(1753.63,574) 1830.77,574 1860.2,603.43 UD1.24@1959.03,603.43 ; v1(1753.63,1020) 1830.77,1020 1860.2,1049.43 UD5.24@1959.03,1049.43 ; v1(1758.63,2640) 1835.77,2640 1865.2,2669.43 ; v1(1763.63,3095) 1840.77,3095 1870.2,3124.43 UD13.24@1969.03,3124.43 ; v1(1831.77,2258.37) RA5.1@1874.27,2258.37 ; UP5.12@1858.3,1480.05 1858.3,1438.7 v1(1872.63,1424.37) ; RA3.1@2041.77,2258.37 v1(2084.27,2258.37) ; 1865.2,2669.43 UD9.24@1964.03,2669.43 1865.2,2669.43 ; v1(1132.63,757.37) CT37.2@1187.63,757.37 v1(1132.63,757.37) ; v1(1132.63,1872.37) CT46.1@1175.63,1872.37 v1(1132.63,1872.37) ; v1(1132.63,2282.37) CT28.1@1174.63,2283.37 v1(1132.63,2282.37) ; v1(1133.63,232.37) CT32.1@1174.63,232.37 v1(1133.63,232.37) ; v1(1133.63,1579.37) CT33.2@1188.63,1579.37 v1(1133.63,1579.37) ; v1(1133.63,1988.37) CT45.2@1188.63,1988.37 v1(1133.63,1988.37) ; v1(1133.63,2398.37) CT27.2@1189.63,2398.37 v1(1133.63,2398.37) ; v1(1133.63,2694.37) CT42.1@1176.63,2694.37 v1(1133.63,2694.37) ; v1(1133.63,3223.37) CT53.2@1188.63,3223.37 v1(1133.63,3223.37) ; v1(1134.63,1169.37) CT49.2@1189.63,1169.37 v1(1134.63,1169.37) ; v1(1134.63,2810.37) CT41.2@1189.63,2810.37 v1(1134.63,2810.37) ; v1(1712.63,1284.37) UP6.1@1712.63,1318.37 v1(1712.63,1284.37)
  Top Layer w8: v1(1801.77,1703.91) 1821.18,1723.32 UA1.50@1821.18,1739.43 ; v1(1801.77,2123.37) 1821.18,2103.95 UA1.31@1821.18,2087.85
  Top Layer w12: v1(1881.77,1553.37) 1996.77,1553.37 2011.77,1568.37 CA33.1@2011.77,1603.37 ; 1964.27,1553.37 RA54.2@1964.27,1603.37
  Top Layer w30: J1.2@1079.63,109 v3(1165.3,109)
  Mid-Layer 1 w30: J1.2@1079.63,109 v3(1165.3,109)
  Mid-Layer 2 w30: J1.2@1079.63,109 v3(1165.3,109)
  Bottom Layer w7: UT35.25@976.03,1423.27 v1(1033.63,1423.27) ; UT35.48@976.03,1784.37 v1(1033.63,1784.37) ; UT50.25@976.03,1832.27 v1(1033.63,1832.27) ; UT50.48@976.03,2193.37 v1(1033.63,2193.37) ; UT31.25@976.03,2242.27 v1(1033.63,2242.27) ; UT31.48@976.03,2603.37 v1(1033.63,2603.37) ; UT60.48@976.03,3428.37 v1(1033.63,3428.37) ; UT32.25@977.03,192.27 v1(1034.63,192.27) ; UT55.48@977.03,1374.37 v1(1034.63,1374.37) ; UT45.48@977.03,3015.37 v1(1032.63,3015.37) ; v1(1034.63,553.37) v1@1032.63,553.37 ; v1@1131.03,1784.37 v1(1133.63,1784.37) ; v1@1131.03,2193.37 v1(1133.63,2193.37) ; v1(1131.63,641.37) 1134.63,641.37 1141.63,648.37 UT40.21@1187.63,648.37 ; v1(1132.63,757.37) 1147.43,742.57 UT40.15@1187.63,742.57 ; v1(1132.63,821.17) v1@1132.73,821.07 ; v1(1132.63,915.37) 1132.73,915.27 UT40.4@1187.63,915.27 ; v1(1132.63,1463.37) 1135.63,1463.37 1142.63,1470.37 UT35.21@1188.63,1470.37 ; v1(1132.63,1872.37) 1135.63,1872.37 1142.63,1879.37 UT50.21@1188.63,1879.37 ; v1(1132.63,2282.37) 1135.63,2282.37 1142.63,2289.37 UT31.21@1188.63,2289.37 ; v1(1132.63,3107.37) 1135.63,3107.37 1142.63,3114.37 UT60.21@1188.63,3114.37 ; v1(1133.63,232.37) 1136.63,232.37 1143.63,239.37 UT32.21@1189.63,239.37 ; v1(1133.63,1053.37) 1136.63,1053.37 1143.63,1060.37 UT55.21@1189.63,1060.37 ; v1(1133.63,1579.37) 1148.43,1564.57 UT35.15@1188.63,1564.57 ; v1(1133.63,1737.37) v1@1133.73,1737.27 ; v1(1133.63,1988.37) 1133.63,1987.77 1147.83,1973.57 UT50.15@1188.63,1973.57 ; v1(1133.63,2146.37) v1@1133.73,2146.27 ; v1(1133.63,2398.37) 1148.43,2383.57 UT31.15@1188.63,2383.57 ; v1(1133.63,2462.17) v1@1133.73,2462.07 ; v1(1133.63,2694.37) 1136.63,2694.37 1143.63,2701.37 UT45.21@1189.63,2701.37 ; v1(1133.63,3223.37) 1133.63,3221.77 1146.83,3208.57 UT60.15@1188.63,3208.57 ; v1(1134.63,343) v1@1140.9,349.27 ; v1@1134.63,412.17 v1(1134.73,412.07) UT32.10@1189.63,412.07 ; v1(1134.63,1169.37) 1135.03,1169.37 1149.83,1154.57 UT55.15@1189.63,1154.57 ; v1(1134.63,1233.17) v1@1134.73,1233.07 ; v1(1134.63,1327.37) 1134.73,1327.27 UT55.4@1189.63,1327.27 ; v1(1134.63,2810.37) 1135.03,2810.37 1149.83,2795.57 UT45.15@1189.63,2795.57 ; UT31.4@1188.63,2556.27 v1@1133.73,2556.27 ; UT60.4@1188.63,3381.27 v1@1133.73,3381.27 ; 1189.63,193 UT32.23@1189.63,207.97 UT32.22@1189.63,223.67 UT32.21@1189.63,239.37 ; 1189.63,208 RP35.2@1264.63,208 pad.1@1304.63,208 ; UT32.19@1189.63,270.77 UT32.20@1189.63,255.07 UT32.21@1189.63,239.37 ; UT32.17@1189.63,302.17 UT32.16@1189.63,317.87 UT32.15@1189.63,333.57 1189.63,343.37 UT32.14@1189.63,349.27 ; UT45.4@1189.63,2968.27 v1@1134.73,2968.27 ; v1(1349.63,1286) 1349.63,1299 CP3.1@1372.63,1322 ; RP8.2@1356.63,2437 pad.1@1356.63,2492 ; UP1.4@1489.63,1372.2 1516.43,1372.2 v3(1541.63,1347) ; RP6.2@1554.63,1393 1541.63,1380 ; v1(1710.63,2403) RP37.1@1710.63,2449 ; RP36.1@1724.63,2909 1715.63,2900 v1(1715.63,2863) ; v1(1731.63,342) RP40.1@1731.63,388 ; v1@1031.63,3066.37 v1(1032.63,3066.37) v1@1031.63,3066.37 ; v1@1031.63,3066.37 v1@1032.53,3067.27 ; v1@1032.53,3067.27 UT60.25@976.03,3067.27 v1@1032.53,3067.27 ; v1@1032.63,553.37 UT32.48@977.03,553.37 v1@1032.63,553.37 ; v1@1132.73,821.07 UT40.10@1187.63,821.07 v1@1132.73,821.07 ; v1(1133.63,1784.37) UT35.1@1188.63,1784.37 v1(1133.63,1784.37) ; v1(1133.63,2193.37) UT50.1@1188.63,2193.37 v1(1133.63,2193.37) ; v1@1133.73,1643.07 v1(1133.63,1643.17) v1@1133.73,1643.07 ; v1@1133.73,1643.07 UT35.10@1188.63,1643.07 v1@1133.73,1643.07 ; v1@1133.73,1737.27 UT35.4@1188.63,1737.27 v1@1133.73,1737.27 ; v1@1133.73,2052.07 v1(1133.63,2052.17) v1@1133.73,2052.07 ; v1@1133.73,2052.07 UT50.10@1188.63,2052.07 v1@1133.73,2052.07 ; v1@1133.73,2146.27 UT50.4@1188.63,2146.27 v1@1133.73,2146.27 ; v1@1133.73,2462.07 UT31.10@1188.63,2462.07 v1@1133.73,2462.07 ; v1@1133.73,2556.27 v1(1133.63,2556.37) v1@1133.73,2556.27 ; v1@1133.73,3287.07 v1(1133.63,3287.17) v1@1133.73,3287.07 ; v1@1133.73,3287.07 UT60.10@1188.63,3287.07 v1@1133.73,3287.07 ; v1@1133.73,3381.27 v1(1133.63,3381.37) v1@1133.73,3381.27 ; v1@1134.73,1233.07 UT55.10@1189.63,1233.07 v1@1134.73,1233.07 ; v1@1134.73,2874.07 v1(1134.63,2874.17) v1@1134.73,2874.07 ; v1@1134.73,2874.07 UT45.10@1189.63,2874.07 v1@1134.73,2874.07 ; v1@1134.73,2968.27 v1(1134.63,2968.37) v1@1134.73,2968.27 ; v1@1140.9,349.27 UT32.14@1189.63,349.27 ; v1@1140.9,349.27 UT32.14@1189.63,349.27 ; v3(1541.63,1347) 1541.63,1380 ; v3(1541.63,1347) 1541.63,1380 ; v1(1715.63,2863) 1714.63,2864 v1(1715.63,2863) ; UT40.25@975.03,601.27 v1(1032.63,601.27) UT40.25@975.03,601.27 ; UT40.48@975.03,962.37 v1(1032.63,962.37) UT40.48@975.03,962.37 ; UT55.25@977.03,1013.27 v1(1034.63,1013.27) UT55.25@977.03,1013.27 ; UT45.25@977.03,2654.27 v1(1034.63,2654.27) UT45.25@977.03,2654.27 ; v1(1133.63,1423.27) UT35.24@1188.63,1423.27 v1(1133.63,1423.27) ; v1(1133.63,1832.27) UT50.24@1188.63,1832.27 v1(1133.63,1832.27) ; v1@1134.63,192.27 UT32.24@1189.63,192.27 v1@1134.63,192.27 ; v1(1730.63,788) RP39.1@1730.63,834 v1(1730.63,788)
  Bottom Layer w12: v1(1712.63,1284.37) CP22.1@1712.63,1337.37 ; CA45.2@1859.27,1658.91 1816.77,1658.91 1801.77,1673.91 v1(1801.77,1703.91) 1825.27,1727.41 CA25.2@1825.27,1763.91 1859.27,1763.91 ; 1859.27,2063.37 CA7.1@1825.27,2063.37 1825.27,2099.87 v1(1801.77,2123.37) 1801.77,2153.37 1816.77,2168.37 CA44.2@1859.27,2168.37 ; v1(1872.63,1424.37) CP21.2@1872.63,1483.37
  Bottom Layer w20: v3(1541.63,1347) 1566.85,1347 1590.65,1370.8 CP7.2@1625.93,1370.8 ; CA45.2@1859.27,1658.91 RP38.1@1859.27,1913.37 CA44.2@1859.27,2168.37
  Bottom Layer w30: J1.2@1079.63,109 v3(1165.3,109)
  other v1: 1133.63,192.93
GND_EARTH: CP1.1 CP2.1 CP5.2 CP12.2 CP17.1 CT25.2 CT26.1 CT29.2 CT30.1 CT35.2 CT36.1 CT39.2 CT40.1 CT43.2 CT44.1 CT47.2 CT48.1 CT51.2 CT52.1 CT55.2 CT56.1 J1.1 J3.19 J3.20 J3.45 J3.46 J5.25 J5.26 J5.45 J5.46 J5.65 J5.66 J5.75 J5.76 UT31.28 UT31.34 UT31.39 UT31.45 UT32.28 UT32.34 UT32.37 UT32.38 UT32.39 UT32.40 UT32.45 UT35.28 UT35.34 UT35.39 UT35.45 UT40.28 UT40.34 UT40.39 UT40.45 UT45.28 UT45.34 UT45.39 UT45.45 UT50.28 UT50.34 UT50.39 UT50.45 UT55.28 UT55.34 UT55.39 UT55.45 UT60.28 UT60.34 UT60.39 UT60.45 UT74.14 | length 7540.1
  Top Layer w7: v1(115.87,1042.3) J5.45@194.63,1042.3 J5.46@324.55,1042.3 ; v1@403.55,452.6 v1(404.35,451.8) ; v1@403.55,649.43 v1(404.35,648.63) J5.66@324.55,648.63 J5.65@194.63,648.63 ; CP5.2@718.63,1477.37 CP5.2@719.63,1478.37 ; v1(895.63,3194.37) 928.63,3161.37 CT56.1@934.63,3161.37 935.63,3162.37 935.63,3199.37 CT55.2@969.63,3233.37 ; CT29.2@969.63,358.37 940.63,326.37 940.63,289.37 CT30.1@939.63,288.37 ; CT35.2@969.63,1589.37 935.63,1555.37 935.63,1518.37 CT36.1@934.63,1517.37 CT36.1@928.63,1517.37 ; CT47.2@969.63,1998.37 935.63,1964.37 935.63,1927.37 CT48.1@934.63,1926.37 CT48.1@928.63,1926.37 ; CT25.2@969.63,2408.37 935.63,2371.37 935.63,2334.37 CT26.1@934.63,2333.37 ; CT43.2@970.63,2820.37 936.63,2786.37 936.63,2749.37 CT44.1@935.63,2748.37 CT44.1@929.63,2748.37 ; CP1.1@1034.63,744 1032.63,744 1009.63,767 969,767 CT39.2@968.63,767.37 934.63,733.37 934.63,696.37 CT40.1@933.63,695.37 CT40.1@927.63,695.37 ; CP2.1@1039.63,1159 1038.63,1159 1019.63,1178 972,1178 CT51.2@970.63,1179.37 936.63,1145.37 936.63,1108.37 CT52.1@935.63,1107.37 CT52.1@929.63,1107.37 ; J5.65@194.63,648.63 v1(115.87,648.63) J5.65@194.63,648.63 ; CP12.2@689.63,3018 664.63,2993 CP12.2@689.63,3018 ; CP12.2@689.63,3018 CP12.2@689.63,3019 CP12.2@689.63,3018 ; v1@895.63,2369.37 v1(895.63,2372) v1@895.63,2369.37 ; v1@895.63,2369.37 CT26.1@928.63,2336.37 ; v1@895.63,2369.37 895.63,2366.37 928.63,2333.37 CT26.1@934.63,2333.37 ; CT40.1@927.63,695.37 v1(894.63,728.37) CT40.1@927.63,695.37 ; CT36.1@928.63,1517.37 v1(895.63,1550.37) CT36.1@928.63,1517.37 ; CT48.1@928.63,1926.37 v1(895.63,1959.37) CT48.1@928.63,1926.37 ; CT26.1@928.63,2336.37 CT26.1@934.63,2333.37 ; CT26.1@928.63,2336.37 CT26.1@934.63,2333.37 ; CT52.1@929.63,1107.37 v1(896.63,1140.37) CT52.1@929.63,1107.37 ; CT44.1@929.63,2748.37 v1(896.63,2781.37) CT44.1@929.63,2748.37 ; CT30.1@939.63,288.37 933.63,288.37 900.63,321.37 v1(896.63,319.37) 929.63,286.37 CT30.1@939.63,288.37
  Top Layer w12: v1(115.6,479) 142.8,451.8 J5.75@194.63,451.8 ; J5.76@324.55,451.8 v1(404.35,451.8) J5.76@324.55,451.8
  Top Layer w20: v1(105,1449) 118.03,1435.97 J5.25@194.63,1435.97 J5.26@324.55,1435.97 ; v1(115.87,2999.13) J3.19@194.63,2999.13 J3.20@324.55,2999.13 ; J5.75@194.63,451.8 J5.76@324.55,451.8 ; J3.45@194.63,2487.37 J3.46@324.55,2487.37 v1(398.37,2487.37) ; v3(637.63,389) CP17.1@709.63,389 ; v1(718.63,1392) CP5.2@718.63,1477.37 ; v3(595.63,2993) 664.63,2993 v3(595.63,2993)
  Top Layer w30: v3(893.97,109) J1.1@979.63,109
  Mid-Layer 1 w30: v3(893.97,109) J1.1@979.63,109
  Mid-Layer 2 w30: v3(893.97,109) J1.1@979.63,109
  Bottom Layer w7: v1(884.63,821.37) 888.63,821.37 888.83,821.17 904.63,821.17 ; v1(885.63,2052.37) 889.63,2052.37 889.83,2052.17 905.63,2052.17 ; v1(885.63,2462.37) 889.63,2462.37 889.83,2462.17 905.63,2462.17 ; v1(886.63,1233.37) 890.63,1233.37 890.83,1233.17 906.63,1233.17 ; v1(886.63,2874.37) 890.63,2874.37 890.83,2874.17 906.63,2874.17 ; v1(894.63,728.37) 909.63,728.37 923.83,742.57 UT40.34@975.03,742.57 ; v1(895.63,1550.37) 910.63,1550.37 924.83,1564.57 UT35.34@976.03,1564.57 ; v1(895.63,1959.37) 910.63,1959.37 924.83,1973.57 UT50.34@976.03,1973.57 ; v1(895.63,2372) 912,2372 923.2,2383.57 UT31.34@976.03,2383.57 ; v1(895.63,3194.37) 910.63,3194.37 924.83,3208.57 UT60.34@976.03,3208.57 ; v1(896.63,319.37) 911.63,319.37 925.83,333.57 UT32.34@977.03,333.57 ; v1(896.63,1140.37) 911.63,1140.37 925.83,1154.57 UT55.34@977.03,1154.57 ; v1(896.63,2781.37) 911.63,2781.37 925.83,2795.57 UT45.34@977.03,2795.57 ; v1(897.63,632.37) 914.63,632.37 930.63,648.37 ; v1(898.63,1454.37) 915.63,1454.37 930.63,1469.37 941.63,1469.37 942.63,1470.37 ; v1(898.63,2273.37) 916,2273.37 931.63,2289 948.63,2289 949,2289.37 UT31.28@976.03,2289.37 ; v1(898.63,3098.37) 915.63,3098.37 931.63,3114.37 UT60.28@976.03,3114.37 ; v1(899.63,2685.37) 916.63,2685.37 932.63,2701.37 UT45.28@977.03,2701.37 ; v1(901.63,915.37) 904.63,915.37 UT40.45@975.03,915.27 ; v1(902.63,1737.37) 905.63,1737.37 UT35.45@976.03,1737.27 ; v1(902.63,3381.37) 905.63,3381.37 UT60.45@976.03,3381.27 ; v1(903.63,1327.37) 906.63,1327.37 UT55.45@977.03,1327.27 ; v1(917.63,412) 917.7,412.07 UT32.39@977.03,412.07 ; UT50.28@976.03,1879.37 931.63,1879.37 915.63,1863.37 ; UT50.45@976.03,2146.27 v1@905.63,2146.37 ; UT31.45@976.03,2556.27 v1@905.63,2556.37 ; UT32.37@977.03,380.67 UT32.38@977.03,396.37 UT32.39@977.03,412.07 ; 977.03,412.4 UT32.40@977.03,427.77 UT32.39@977.03,412.07 ; UT55.28@977.03,1060.37 932.63,1060.37 916.63,1044.37 ; v1@889.63,1643.37 v1(885.63,1643.37) v1@889.63,1643.37 ; v1@889.63,1643.37 889.83,1643.17 905.63,1643.17 ; v1@889.63,3287.37 v1(885.63,3287.37) v1@889.63,3287.37 ; v1@889.63,3287.37 889.83,3287.17 905.63,3287.17 ; 904.63,821.17 UT40.39@975.03,821.07 904.63,821.17 ; 905.63,1643.17 UT35.39@976.03,1643.07 905.63,1643.17 ; 905.63,2052.17 UT50.39@976.03,2052.07 905.63,2052.17 ; v1@905.63,2146.37 v1(902.63,2146.37) v1@905.63,2146.37 ; 905.63,2462.17 UT31.39@976.03,2462.07 905.63,2462.17 ; v1@905.63,2556.37 v1(902.63,2556.37) v1@905.63,2556.37 ; 905.63,3287.17 UT60.39@976.03,3287.07 905.63,3287.17 ; v1@906.63,506.37 v1(903.63,506.37) v1@906.63,506.37 ; v1@906.63,506.37 UT32.45@977.03,506.27 v1@906.63,506.37 ; 906.63,1233.17 UT55.39@977.03,1233.07 906.63,1233.17 ; 906.63,2874.17 UT45.39@977.03,2874.07 906.63,2874.17 ; v1@906.63,2968.37 UT45.45@977.03,2968.27 v1@906.63,2968.37 ; v1@906.63,2968.37 v1(903.63,2968.37) v1@906.63,2968.37 ; 915.63,1863.37 v1(898.63,1863.37) 915.63,1863.37 ; 916.63,223.37 v1(899.63,223.37) 916.63,223.37 ; 916.63,223.37 932.63,239.37 ; 916.63,1044.37 v1(897.63,1044.37) 916.63,1044.37 ; 930.63,648.37 UT40.28@975.03,648.37 930.63,648.37 ; 932.63,239.37 UT32.28@977.03,239.37 932.63,239.37 ; 942.63,1470.37 UT35.28@976.03,1470.37 942.63,1470.37 ; UT74.14@744.13,2355.37 v1(779.63,2355.37) UT74.14@744.13,2355.37
  Bottom Layer w30: v3(893.97,109) J1.1@979.63,109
